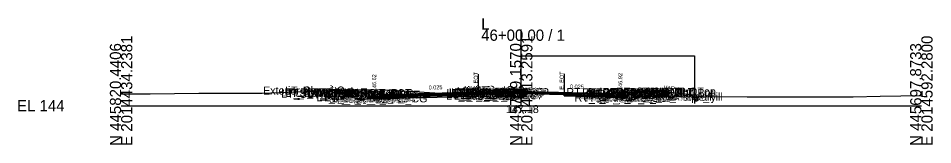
# Model space of a CAD drawing. Extents: x -26 to 4203, y -10 to 9526.
# Drawn here: x 2974.3 to 3202.8, y 5990.3 to 6021.8 of the extents above; entities that cross this region are included whole.
import ezdxf

# ---------------------------------------------------------------- set-up
doc = ezdxf.new("R2010")
doc.units = 0
for name, color, linetype in [('Default', 7, 'Continuous'), ('Exist CMT Pavement', 7, 'Continuous'), ('Exist Cross Section Cell', 7, 'Continuous'), ('Exist XS Center Line Elevation Label', 7, 'Continuous'), ('Exist XS Ground Line', 7, 'Continuous'), ('Prop CMT Conc Surface', 7, 'Continuous'), ('Prop CMT Concrete Structures', 7, 'Continuous'), ('Prop CMT Pvmt Course 1', 7, 'Continuous'), ('Prop CMT Pvmt Course 1 CG', 7, 'Continuous'), ('Prop CMT Pvmt Course 1 Wedge', 7, 'Continuous'), ('Prop CMT Pvmt Course 2', 7, 'Continuous'), ('Prop CMT Pvmt Course 2 Wedge', 7, 'Continuous'), ('Prop CMT Pvmt Course 3', 7, 'Continuous'), ('Prop CMT Pvmt Course 3 Wedge', 7, 'Continuous'), ('Prop CMT Pvmt Surface', 7, 'Continuous'), ('Prop CMT Pvmt Wedge Surface 1', 7, 'Continuous'), ('Prop CMT Pvmt Wedge Surface 2', 7, 'Continuous'), ('Prop CMT Pvmt Wedge Surface 3', 7, 'Continuous'), ('Prop CMT Slope Grass', 7, 'Continuous'), ('Prop CMT Subgrade Earthwork', 7, 'Continuous'), ('Prop XS Finish Grade CurbGutter', 7, 'Continuous'), ('Prop XS Hydro Elevations', 7, 'Continuous'), ('Prop XS Label Text', 7, 'Continuous'), ('Prop XS SE Text', 7, 'Continuous'), ('Prop XS Side Slope Text', 7, 'Continuous'), ('Scratch_Level_0', 7, 'Continuous'), ('Scratch_Level_1', 7, 'Continuous')]:
    doc.layers.add(name, color=color, linetype=linetype)

msp = doc.modelspace()

# ---------------------------------------------------------------- linework, layer by layer
at = {"layer": 'Exist CMT Pavement'}
for p, q in [((3089.24, 6002.85), (3092.07, 6002.94)), ((3092.07, 6002.94), (3093.14, 6002.99)), ((3093.14, 6002.99), (3095.33, 6003.05)), ((3095.33, 6003.05), (3098.46, 6003.16)), ((3098.46, 6003.16), (3099.7, 6003.18)), ((3099.7, 6003.18), (3105.59, 6003.04)), ((3105.59, 6003.04), (3107.97, 6002.94)), ((3107.97, 6002.94), (3109.2, 6002.88)), ((3109.2, 6002.88), (3109.88, 6002.87)), ((3109.88, 6002.87), (3110.59, 6002.87)), ((3110.59, 6002.87), (3110.73, 6002.99))]:
    msp.add_line(p, q, dxfattribs=at)
at = {"layer": 'Exist Cross Section Cell'}
for p, q in [((3100, 6000), (3100, 6018.98)), ((3000, 6000), (3100, 6000)), ((3100, 6000), (3200, 6000))]:
    msp.add_line(p, q, dxfattribs=at)
at = {"layer": 'Exist XS Ground Line'}
msp.add_lwpolyline([(3000, 6002.95), (3007.29, 6002.93), (3019.45, 6003.1), (3021.81, 6003.1), (3028.11, 6003.11), (3035.28, 6003.12), (3052.4, 6003.84), (3061.41, 6004.09), (3067.87, 6003.89), (3068.54, 6003.85), (3069.06, 6003.83), (3073.17, 6003.57), (3086.25, 6002.69), (3086.67, 6002.71), (3088.47, 6002.81), (3089.01, 6002.84), (3090.39, 6002.88), (3092.07, 6002.94), (3093.14, 6002.99), (3094.47, 6003.03), (3095.33, 6003.05), (3098.5, 6003.16), (3099.7, 6003.18), (3101.59, 6003.13), (3102.03, 6003.12), (3102.59, 6003.11), (3103.81, 6003.07), (3104.75, 6003.06), (3105.59, 6003.04), (3106.66, 6002.99), (3107.39, 6002.97), (3107.97, 6002.94), (3109.2, 6002.88), (3109.88, 6002.87), (3110.59, 6002.87), (3110.73, 6002.99), (3111.17, 6002.81), (3114.53, 6002.78), (3115.07, 6002.79), (3115.59, 6003.2), (3116.9, 6003.15), (3119.89, 6003.05), (3121.66, 6002.99), (3122.84, 6002.94), (3123.69, 6002.91), (3124.33, 6002.89), (3124.84, 6002.87), (3125.25, 6002.85), (3126.14, 6002.81), (3128.02, 6002.69), (3128.52, 6002.29), (3134.34, 6002.28), (3156.43, 6002.21), (3156.83, 6002.21), (3167.56, 6002.2), (3170.31, 6002.2), (3182.11, 6002.23), (3182.96, 6002.24), (3189.72, 6002.39), (3200, 6002.57)], dxfattribs=at)
at = {"layer": 'Prop CMT Conc Surface'}
for points in [[(3129.25, 6003.51), (3134.25, 6003.61)], [(3058.75, 6003.21), (3053.75, 6003.31)], [(3063.25, 6002.62), (3063.25, 6003.12), (3062.75, 6003.12)], [(3065.25, 6002.75), (3063.25, 6002.62)], [(3122.75, 6003.05), (3124.75, 6002.92)], [(3124.75, 6002.92), (3124.75, 6003.42), (3125.25, 6003.42)]]:
    msp.add_lwpolyline(points, dxfattribs=at)
at = {"layer": 'Prop CMT Concrete Structures'}
for points in [[(3096, 6003.72), (3095.99, 6003.89), (3095.24, 6004.14), (3094, 6004.16), (3092.76, 6003.84), (3092.01, 6003.59), (3092, 6003.42)], [(3092, 6003.42), (3096, 6003.72)], [(3134.25, 6003.61), (3129.25, 6003.51)], [(3134.25, 6003.28), (3134.25, 6003.61)], [(3053.75, 6002.98), (3053.75, 6003.31)], [(3053.75, 6003.31), (3058.75, 6003.21)], [(3058.75, 6002.88), (3053.75, 6002.98)], [(3058.75, 6003.21), (3058.75, 6002.88)], [(3065.25, 6002.75), (3063.25, 6002.62), (3063.25, 6003.12), (3062.75, 6003.12)], [(3062.75, 6003.12), (3062.75, 6002.11), (3065.25, 6002.17)], [(3065.25, 6002.17), (3065.25, 6002.75)], [(3122.75, 6003.05), (3124.75, 6002.92), (3124.75, 6003.42), (3125.25, 6003.42)], [(3125.25, 6003.42), (3125.25, 6002.41), (3122.75, 6002.47)], [(3122.75, 6002.47), (3122.75, 6003.05)], [(3129.25, 6003.51), (3129.25, 6003.18)], [(3129.25, 6003.18), (3134.25, 6003.28)]]:
    msp.add_lwpolyline(points, dxfattribs=at)
at = {"layer": 'Prop CMT Pvmt Course 1'}
for points in [[(3092, 6003.42), (3096, 6003.72)], [(3096, 6003.72), (3096, 6003.47)], [(3096, 6003.72), (3122.75, 6003.05)], [(3096, 6003.47), (3096, 6003.72)], [(3110.73, 6003.23), (3096, 6003.6)], [(3096, 6003.6), (3096, 6003.47), (3096, 6003.47)], [(3086.25, 6003.28), (3065.25, 6002.75)], [(3065.25, 6002.5), (3086.25, 6003.03)], [(3065.25, 6002.75), (3065.25, 6002.5)], [(3089.24, 6003.1), (3089.24, 6003.23)], [(3096, 6003.47), (3092, 6003.17)], [(3092, 6003.17), (3092, 6003.42)], [(3092, 6003.17), (3092, 6003.42)], [(3092, 6003.3), (3092, 6003.17), (3092, 6003.17)], [(3110.73, 6003.1), (3110.73, 6003.23)], [(3122.75, 6002.8), (3114.21, 6003.02)], [(3122.75, 6003.05), (3122.75, 6002.8)]]:
    msp.add_lwpolyline(points, dxfattribs=at)
at = {"layer": 'Prop CMT Pvmt Course 1 CG'}
for points in [[(3065.25, 6002.17), (3062.25, 6002.09), (3061.91, 6001.75)], [(3061.91, 6001.75), (3065.25, 6001.84)], [(3065.25, 6001.84), (3065.25, 6002.17)], [(3122.75, 6002.47), (3125.75, 6002.39), (3126.09, 6002.05)], [(3122.75, 6002.14), (3122.75, 6002.47)], [(3126.09, 6002.05), (3122.75, 6002.14)]]:
    msp.add_lwpolyline(points, dxfattribs=at)
at = {"layer": 'Prop CMT Pvmt Course 1 Wedge'}
for points in [[(3096, 6003.47), (3096, 6003.6)], [(3096, 6003.6), (3098.46, 6003.53), (3098.49, 6003.53), (3098.5, 6003.53), (3099.7, 6003.5), (3099.88, 6003.5), (3101.59, 6003.46), (3102.03, 6003.45), (3102.59, 6003.43), (3103.81, 6003.4), (3104.75, 6003.38), (3105.59, 6003.36), (3106.66, 6003.33), (3107.39, 6003.31), (3107.97, 6003.3), (3109.2, 6003.27), (3109.88, 6003.25), (3110.29, 6003.24), (3110.47, 6003.23), (3110.57, 6003.23), (3110.59, 6003.23), (3110.73, 6003.23)], [(3092, 6003.17), (3090.39, 6003.13), (3089.3, 6003.1), (3089.01, 6003.1), (3088.47, 6003.08), (3086.67, 6003.04), (3086.51, 6003.03), (3086.49, 6003.03), (3086.25, 6003.03), (3086.25, 6003.03)], [(3089.24, 6003.1), (3089.24, 6003.23)], [(3092, 6003.3), (3092, 6003.17)], [(3110.73, 6003.1), (3110.59, 6003.11), (3110.57, 6003.11), (3110.47, 6003.11), (3110.29, 6003.11), (3109.88, 6003.12), (3109.2, 6003.14), (3107.97, 6003.17), (3107.39, 6003.19), (3106.66, 6003.2), (3105.59, 6003.23), (3104.75, 6003.25), (3103.81, 6003.28), (3102.59, 6003.31), (3102.03, 6003.32), (3101.59, 6003.33), (3099.88, 6003.37), (3099.7, 6003.38), (3098.5, 6003.41), (3098.49, 6003.41), (3098.46, 6003.41), (3096, 6003.47)], [(3110.73, 6003.23), (3110.73, 6003.1)]]:
    msp.add_lwpolyline(points, dxfattribs=at)
at = {"layer": 'Prop CMT Pvmt Course 2'}
for points in [[(3086.25, 6003.03), (3065.25, 6002.5)], [(3065.25, 6002.17), (3086.25, 6002.69)], [(3065.25, 6002.5), (3065.25, 6002.17)], [(3089.24, 6002.77), (3089.24, 6003.1)], [(3092, 6003.17), (3096, 6003.47)], [(3092, 6002.84), (3092, 6003.17)], [(3096, 6003.14), (3092, 6002.84)], [(3096, 6003.47), (3096, 6003.14)], [(3110.73, 6002.77), (3110.73, 6003.1)], [(3110.73, 6003.1), (3122.75, 6002.8)], [(3122.75, 6002.47), (3114.21, 6002.68)], [(3122.75, 6002.8), (3122.75, 6002.47)]]:
    msp.add_lwpolyline(points, dxfattribs=at)
at = {"layer": 'Prop CMT Pvmt Course 2 Wedge'}
for points in [[(3086.25, 6003.03), (3086.25, 6003.03), (3086.49, 6003.03), (3086.51, 6003.03), (3086.67, 6003.04), (3088.47, 6003.08), (3089.01, 6003.1), (3089.3, 6003.1), (3090.39, 6003.13), (3092, 6003.17)], [(3092, 6002.94), (3090.39, 6002.88), (3089.3, 6002.85), (3089.01, 6002.84), (3088.47, 6002.81), (3086.67, 6002.71), (3086.51, 6002.71), (3086.49, 6002.71), (3086.35, 6002.7), (3086.25, 6002.69), (3086.25, 6002.69)], [(3089.24, 6002.77), (3089.24, 6003.1)], [(3092, 6003.17), (3092, 6002.94)], [(3096, 6003.14), (3096, 6003.47)], [(3096, 6003.47), (3098.46, 6003.41), (3098.49, 6003.41), (3098.5, 6003.41), (3099.7, 6003.38), (3099.88, 6003.37), (3101.59, 6003.33), (3102.03, 6003.32), (3102.59, 6003.31), (3103.81, 6003.28), (3104.75, 6003.25), (3105.59, 6003.23), (3106.66, 6003.2), (3107.39, 6003.19), (3107.97, 6003.17), (3109.2, 6003.14), (3109.88, 6003.12), (3110.29, 6003.11), (3110.47, 6003.11), (3110.57, 6003.11), (3110.59, 6003.11), (3110.73, 6003.1)], [(3114.21, 6002.79), (3111.17, 6002.81), (3111.01, 6002.82), (3110.94, 6002.87), (3110.73, 6002.99), (3110.59, 6002.87), (3110.57, 6002.85), (3110.47, 6002.86), (3110.29, 6002.86), (3109.88, 6002.87), (3109.2, 6002.88), (3107.97, 6002.94), (3107.39, 6002.97), (3106.66, 6002.99), (3105.59, 6003.04), (3104.75, 6003.06), (3103.81, 6003.07), (3102.59, 6003.11), (3102.03, 6003.12), (3101.59, 6003.13), (3099.88, 6003.18), (3099.7, 6003.18), (3098.5, 6003.16), (3098.49, 6003.16), (3098.46, 6003.16), (3097.04, 6003.11), (3096, 6003.14)], [(3110.73, 6003.1), (3110.73, 6002.87)]]:
    msp.add_lwpolyline(points, dxfattribs=at)
at = {"layer": 'Prop CMT Pvmt Course 3'}
for points in [[(3089.24, 6002.77), (3065.25, 6002.17)], [(3065.25, 6001.84), (3089.24, 6002.43)], [(3065.25, 6002.17), (3065.25, 6001.84)], [(3089.24, 6002.44), (3089.24, 6002.77)], [(3092, 6002.84), (3096, 6003.14)], [(3110.73, 6002.77), (3122.75, 6002.47)], [(3110.73, 6002.44), (3110.73, 6002.77)], [(3122.75, 6002.14), (3110.73, 6002.44)], [(3122.75, 6002.47), (3122.75, 6002.14)]]:
    msp.add_lwpolyline(points, dxfattribs=at)
at = {"layer": 'Prop CMT Pvmt Course 3 Wedge'}
for points in [[(3089.24, 6002.76), (3089.24, 6002.77)], [(3096, 6003.14), (3097.04, 6003.11)], [(3096, 6003.08), (3096, 6003.14)], [(3097.04, 6003.11), (3096, 6003.08)]]:
    msp.add_lwpolyline(points, dxfattribs=at)
at = {"layer": 'Prop CMT Pvmt Surface'}
for points in [[(3092, 6003.42), (3096, 6003.72)], [(3096, 6003.72), (3122.75, 6003.05)], [(3092, 6003.42), (3065.25, 6002.75)]]:
    msp.add_lwpolyline(points, dxfattribs=at)
at = {"layer": 'Prop CMT Pvmt Wedge Surface 1'}
for points in [[(3096, 6003.72), (3096, 6003.47), (3096, 6003.47), (3096, 6003.6)], [(3096, 6003.6), (3110.73, 6003.23)], [(3089.24, 6003.23), (3089.24, 6003.1)], [(3092, 6003.42), (3092, 6003.17), (3092, 6003.17), (3092, 6003.3)], [(3110.73, 6003.23), (3110.73, 6003.1)], [(3110.73, 6003.1), (3122.75, 6002.8)], [(3122.75, 6002.8), (3122.75, 6003.05)]]:
    msp.add_lwpolyline(points, dxfattribs=at)
at = {"layer": 'Prop CMT Pvmt Wedge Surface 2'}
for points in [[(3096, 6003.72), (3096, 6003.47)], [(3092, 6003.42), (3092, 6003.17)], [(3096, 6003.47), (3110.73, 6003.1)], [(3122.75, 6002.8), (3122.75, 6003.05)]]:
    msp.add_lwpolyline(points, dxfattribs=at)
at = {"layer": 'Prop CMT Pvmt Wedge Surface 3'}
for points in [[(3096, 6003.72), (3096, 6003.14)], [(3092, 6003.42), (3092, 6002.84)], [(3096, 6003.14), (3110.73, 6002.77)], [(3122.75, 6002.47), (3122.75, 6003.05)]]:
    msp.add_lwpolyline(points, dxfattribs=at)
at = {"layer": 'Prop CMT Slope Grass'}
for points in [[(3051.76, 6003.81), (3053.25, 6003.31)], [(3125.25, 6003.42), (3134.25, 6003.6)], [(3134.25, 6003.6), (3134.75, 6003.61), (3143.3, 6002.75)], [(3062.75, 6003.12), (3053.25, 6003.31)], [(3143.3, 6002.75), (3143.3, 6001.25), (3143.97, 6001.25), (3143.97, 6002.25)]]:
    msp.add_lwpolyline(points, dxfattribs=at)
at = {"layer": 'Prop CMT Subgrade Earthwork'}
for points in [[(3065.25, 6001.84), (3061.91, 6001.75), (3060.49, 6003.17)], [(3089.24, 6002.43), (3065.25, 6001.84)], [(3089.24, 6002.44), (3089.24, 6002.85)], [(3110.73, 6002.44), (3110.73, 6002.99)], [(3110.73, 6002.44), (3122.75, 6002.14)], [(3122.75, 6002.14), (3126.09, 6002.05), (3127.51, 6003.47)]]:
    msp.add_lwpolyline(points, dxfattribs=at)
at = {"layer": 'Prop XS Finish Grade CurbGutter'}
for p, q in [((3143.3, 6002.75), (3143.49, 6002.75)), ((3143.3, 6002.75), (3143.97, 6002.75)), ((3143.3, 6002.75), (3143.3, 6001.75)), ((3143.3, 6001.75), (3143.3, 6001.25)), ((3143.3, 6001.75), (3143.97, 6001.75)), ((3143.97, 6002.33), (3143.61, 6002.7)), ((3143.97, 6002.33), (3143.97, 6001.75)), ((3143.97, 6002.25), (3143.97, 6002.25)), ((3143.97, 6001.75), (3143.97, 6001.25)), ((3143.3, 6001.25), (3143.97, 6001.25))]:
    msp.add_line(p, q, dxfattribs=at)
msp.add_arc((3143.49, 6002.58), 0.166, 43.9997, 90, dxfattribs=at)
at = {"layer": 'Prop XS Label Text'}
for p, q in [((3089.24, 6007.85), (3089.24, 6002.85)), ((3110.73, 6007.99), (3110.73, 6002.99))]:
    msp.add_line(p, q, dxfattribs=at)
at = {"layer": 'Scratch_Level_1'}
msp.add_lwpolyline([(3100, 6012.44), (3143.3, 6012.44), (3143.3, 6000.56)], dxfattribs=at)

# ---------------------------------------------------------------- texts
at = {"layer": 'Default'}
msp.add_text('-', height=0.0001, dxfattribs=at).set_placement((3000, 6000))
at = {"layer": 'Exist Cross Section Cell'}
for s, p in [('L', (3090, 6018.98)), ('46+00.00 / 1', (3090, 6016.18)), ('EL 144', (2974, 5998.6))]:
    msp.add_text(s, height=2.8, dxfattribs=at).set_placement(p)
for s, p in [('E 2014434.2381', (3002.8, 5990)), ('E 2014513.2591', (3102.8, 5990)), ('E 2014592.2800', (3202.8, 5990)), ('N 445820.4406', (3000, 5990)), ('N 445759.1570', (3100, 5990)), ('N 445697.8733', (3200, 5990))]:
    msp.add_text(s, height=2.8, rotation=90, dxfattribs=at).set_placement(p)
at = {"layer": 'Exist XS Center Line Elevation Label'}
msp.add_text('147.18', height=2, dxfattribs=at).set_placement((3096.2, 5998.18))
at = {"layer": 'Prop XS Hydro Elevations'}
for s, p in [('146.62', (3063.75, 6003.62)), ('146.92', (3125.25, 6003.92))]:
    msp.add_text(s, height=1, rotation=90, dxfattribs=at).set_placement(p)
at = {"layer": 'Prop XS Label Text'}
for p in [(3089.14, 6003.87), (3110.63, 6004.01)]:
    msp.add_text('E. EOT', height=1, rotation=90, dxfattribs=at).set_placement(p)
at = {"layer": 'Prop XS SE Text'}
for rotation, p in [(1.4327, (3076.87, 6004.04)), (358.5675, (3112.17, 6004.32))]:
    msp.add_text('0.025', height=1, rotation=rotation, dxfattribs=at).set_placement(p)
at = {"layer": 'Prop XS Side Slope Text'}
for s, rotation, p in [('3:1', 341.5651, (3051.9, 6004.21)), ('VAR.', 354.2297, (3135.53, 6004.1))]:
    msp.add_text(s, height=1, rotation=rotation, dxfattribs=at).set_placement(p)
at = {"layer": 'Scratch_Level_0'}
for s, p in [('Exterior Boundary', (3035.48, 6002.79)), ('LT_SDWK_Out_Top', (3039.99, 6002.31)), ('LT_SDWK_Out_Bot', (3040.02, 6001.98)), ('LT_Slope_Cut', (3040.97, 6002.79)), ('LT_Sub_Trench_Out_DLT', (3041.06, 6002.17)), ('LT_CSLP_Pnt', (3043.42, 6002.31)), ('LT_SDWK_In_Top', (3046.61, 6002.21)), ('LT_SDWK_In_Bot', (3046.64, 6001.88)), ('LT_CG_Top_Face', (3050.51, 6002.12)), ('LT_CG_Top_BOC', (3051.03, 6002.12)), ('LT_CG_Top_Gut', (3051.49, 6001.62)), ('LT_PV1_OEOT', (3055.99, 6001.75)), ('LT_Sub_OEEOP', (3081.21, 6001.5)), ('LT_PV2_OEEOP', (3081.31, 6002.17)), ('LT_PV3_OEEOP', (3081.31, 6001.84)), ('LT_PV1_OEEOP', (3081.87, 6002.3)), ('LT_PV2_IEEOP', (3081.95, 6002.17)), ('LT_PV1_IEEOP', (3082.52, 6002.3)), ('LT_PV2_PGL1', (3082.88, 6002.17)), ('LT_PV3_PGL1', (3082.88, 6001.84)), ('LT_PV2_PGL', (3083.21, 6002.17)), ('LT_PV1_PGL', (3083.78, 6002.42)), ('MI_Face In', (3083.9, 6002.59)), ('RT_Sub_OEEOP', (3085.17, 6001.6)), ('RT_PV2_OEEOP', (3085.26, 6002.27)), ('RT_PV3_OEEOP', (3085.26, 6001.94)), ('MI_Top In', (3085.61, 6002.84)), ('RT_PV1_OEEOP', (3085.83, 6002.4)), ('RT_PV2_IEEOP', (3085.91, 6002.27)), ('MI_Face Out', (3086.26, 6002.69)), ('MI_Top Out', (3086.47, 6002.94)), ('RT_PV1_IEEOP', (3086.47, 6002.4)), ('RT_PV2_PGL1', (3086.83, 6002.47)), ('RT_PV3_PGL1', (3086.83, 6002.14)), ('MI_Crown', (3087.07, 6002.96)), ('RT_PV2_PGL', (3087.17, 6002.27)), ('RT_PV4_PGL', (3087.17, 6001.8)), ('MI_Bot Out', (3087.26, 6002.52)), ('RT_PV1_PGL', (3087.73, 6002.52)), ('RT_Sub_Trench_Out_DLT', (3111.28, 6002.39)), ('RT_CG_Top_Face', (3115.21, 6002.34)), ('RT_PV2_OEOT', (3116.13, 6001.72)), ('RT_CG_Top_Gut', (3116.19, 6001.84)), ('RT_PV1_OEOT', (3116.69, 6001.97)), ('RT_CG_Top_BOC', (3116.74, 6002.34)), ('RT_SDWK_In_Top', (3120.31, 6002.43)), ('RT_SDWK_In_Bot', (3120.34, 6002.1)), ('RT_SDWK_Out_Top', (3123.69, 6002.53)), ('RT_SDWK_Out_Bot', (3123.72, 6002.2)), ('RT_Shld_O', (3130.04, 6002.52)), ('CSLP_Pnt', (3130.87, 6002.53)), ('LT_CG1_Shelf_Out', (3048.8, 6001.09)), ('LT_CG_Bot_BOC', (3051.07, 6001.11)), ('LT_Sub_OEOP', (3052.02, 6000.75)), ('LT_Sub_OEOT_CG', (3052.62, 6000.84)), ('LT_CG_Bot_IE', (3055.16, 6001.17)), ('LT_Sub_OEOT', (3055.33, 6000.84)), ('LT_PV2_OEOT', (3055.42, 6001.5)), ('LT_PV3_OEOT', (3055.42, 6001.17)), ('LT_PV4_PGL', (3083.21, 6001.51)), ('RT_Sub_OEOT_CG', (3113.32, 6001.05)), ('RT_CG1_Shelf_Out', (3115.5, 6001.31)), ('RT_CG_Bot_IE', (3115.87, 6001.39)), ('RT_Sub_OEOT', (3116.03, 6001.05)), ('RT_PV3_OEOT', (3116.13, 6001.39)), ('RT_CG_Bot_BOC', (3116.77, 6001.32)), ('RT_Sub_OEOP', (3119.4, 6000.97)), ('Exterior Boundary', (3127.26, 6001.25)), ('RT_Slope_Fill', (3133.59, 6001.25))]:
    msp.add_text(s, height=2, dxfattribs=at).set_placement(p)

doc.saveas('drawing.dxf')
